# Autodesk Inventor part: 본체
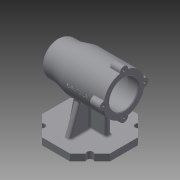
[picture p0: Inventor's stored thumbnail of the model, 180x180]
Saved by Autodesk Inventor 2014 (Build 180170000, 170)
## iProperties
Created: 2021-01
Part Number: 본체
Material: Generic
Document SubType Name: Modeling
Designer: kh
Density: 1 g/cm^3
Appearance: Default
Author: kh
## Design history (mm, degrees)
sketch "Sketch1" dims "d0" = 100
  geometry: L1 (20.711, 50)-(50, 20.711); L2 (50, 20.711)-(50, -20.711); L3 (50, -20.711)-(20.711, -50); L4 (20.711, -50)-(-20.711, -50); L5 (-20.711, -50)-(-50, -20.711); L6 (-50, -20.711)-(-50, 20.711); L7 (-50, 20.711)-(-20.711, 50); L8 (-20.711, 50)-(20.711, 50); 4 further points
  constraints: 16 end point, 2 coincident, 1 horizontal, 1 midpoint, 1 vertical alignment, 19 other
extrude "Extrusion1" new body sketch "Sketch1" distance "d1" = 10; taper "d2" = 0 deg
sketch "Sketch2"
  geometry: L1 (50, 20.711)-(20.711, 50) reference; L2 (20.711, 50)-(-20.711, 50) reference; L3 (-20.711, 50)-(-50, 20.711) reference; L4 (-50, 20.711)-(-50, -20.711) reference; L5 (-50, -20.711)-(-20.711, -50) reference; L6 (-20.711, -50)-(20.711, -50) reference; L7 (20.711, -50)-(50, -20.711) reference; L8 (50, -20.711)-(50, 20.711) reference; L9 (-35.355, 35.355)-(35.355, -35.355); L10 (35.355, 35.355)-(-35.355, -35.355); C1 r 4.5 at (35.355, 35.355); C2 r 4.5 at (35.355, -35.355); C3 r 4.5 at (-35.355, -35.355); C4 r 4.5 at (-35.355, 35.355); 2 further points
  constraints: 5 midpoint, 4 centre point, 4 coincident, 4 end point, 2 perpendicular, 1 point on line
  dimensions: "d3" = 9 diameter of C1; "d4" = 9 diameter of C2; "d5" = 9 diameter of C3; "d6" = 9 diameter of C4
extrude "Extrusion2" cut sketch "Sketch2" stored distance "d7" = 0; taper "d8" = 0 deg
sketch "Sketch3"
  geometry: L1 (0, 0)-(0, 75); L2 (-50, 0)-(-50, 10) reference; L3 (-50, 75)-(50, 75); L4 (50, 75)-(50, 100); L5 (50, 100)-(30, 100); L6 (30, 100)-(10, 105); L7 (10, 105)-(-50, 105); L8 (-50, 105)-(-50, 75); L9 (-50, 96)-(-35, 96); L10 (-35, 96)-(-35, 75); L11 (-35, 75)-(-50, 75); L12 (-50, 75)-(-50, 96); L13 (-35, 75)-(7, 75); L14 (7, 75)-(7, 99); L15 (7, 99)-(-35, 99); L16 (-35, 99)-(-35, 75); L17 (7, 75)-(19, 75); L18 (19, 75)-(19, 96); L19 (19, 96)-(7, 96); L20 (7, 96)-(7, 75); L21 (19, 75)-(37, 75); L22 (37, 75)-(37, 92.5); L23 (37, 92.5)-(19, 92.5); L24 (19, 92.5)-(19, 75); L25 (37, 75)-(41, 75); L26 (41, 75)-(41, 91); L27 (41, 91)-(37, 91); L28 (37, 91)-(37, 75); L29 (41, 75)-(44, 75); L30 (44, 75)-(44, 85.5); L31 (44, 85.5)-(41, 85.5); L32 (41, 85.5)-(41, 75)
  constraints: 62 end point, 15 parallel, 8 perpendicular, 6 horizontal, 2 point on line, 1 collinear, 1 midpoint, 1 vertical
  dimensions: "d9" = 75 distance of L1.start L1.end; "d10" = 60 diameter of L7 L3; "d11" = 50 diameter of L5 L3; "d12" = 20 distance from line of L5.end L4; "d13" = 40 distance from line of L6.end L4; "d14" = 100 distance between parallel lines of L8 L4; "d15" = 15 distance between parallel lines of L8 L10; "d16" = 42 distance between parallel lines of L10 L20; "d17" = 12 distance between parallel lines of L20 L24; "d18" = 18 distance between parallel lines of L24 L22; "d19" = 4 distance of L26.end L27.end; "d20" = 3 distance of L30.end L31.end; "d21" = 21 diameter of L31 L3; "d22" = 32 diameter of L27 L3; "d23" = 35 diameter of L23 L3; "d24" = 48 diameter of L15 L13; "d25" = 42 diameter of L19 L17; "d26" = 42 diameter of L9 L3
revolve "Revolution1" sketch "Sketch3" stored, may be unused: angle "d27" = 90 deg
sketch "Sketch4"
  geometry: L1 (-30, 0)-(30, 0); L2 (0, 30)-(0, -30); C1 r 6 at (-30, 0); C2 r 6 at (0, 30); C3 r 6 at (30, 0); C4 r 6 at (0, -30); A1 r 30 centre (0, 0) between (0, -30) and (-30, 0) reference; 2 further points
  constraints: 5 coincident, 4 centre point, 4 end point, 2 midpoint, 2 point on circle, 1 horizontal, 1 perpendicular
  dimensions: "d28" = 12 diameter of C1; "d29" = 12 diameter of C2 (= d28); "d30" = 12 diameter of C3 (= d28); "d31" = 12 diameter of C4 (= d28)
extrude "Extrusion3" join sketch "Sketch4" distance "d32" = 16; taper "d33" = 0 deg
sketch "Sketch5"
  geometry: L1 (20.711, 0)-(-20.711, 0) reference; L2 (-27, 0)-(-27, 51); L3 (-50, 0)-(-50, 10) reference; L4 (27, 10)-(19.03, 51); L5 (38.537, 10)-(50, 10) reference; L6 (20.711, 10)-(32.173, 10) reference; L7 (50, 0)-(50, 10) reference; L8 (27, 10)-(-27, 10); L9 (19.03, 51)-(-27, 51); L10 (-35, 51)-(7, 51) reference; 1 further point
  constraints: 8 end point, 4 point on line, 2 perpendicular, 1 parallel
  dimensions: "d34" = 23 distance between parallel lines of L3 L2; "d35" = 101 deg angle of L5 L4; "d36" = 23 distance from line of L4.start L7
extrude "Extrusion4" join sketch "Sketch5" stored distance "d37" = 8; taper "d38" = 0 deg
sketch "Sketch6"
  geometry: L1 (-35, 10)-(-23.246, 42.294); L2 (23.02, 42.915)-(35, 10); L3 (0, 0)-(0, 55.467); L4 (-38.537, 10)-(-30.855, 10) reference; L5 (-20.711, 10)-(-32.173, 10) reference; L6 (50, 10)-(38.537, 10) reference; L7 (30.855, 10)-(38.537, 10) reference; L8 (-50, 0)-(-50, 10) reference; 1 further point
  constraints: 6 end point, 2 point on line, 1 vertical, 1 other
  dimensions: "d39" = 15 distance from line of L8 L1.start; "d40" = 110 deg angle of L4 L1
feature "Rib1" dims "d41" = 1, "d42" = 8, "d43" = 0, "d44" = 0, "d45" = 1, "d46" = 1
feature "Rib2" dims "d47" = 1, "d48" = 8, "d49" = 0, "d50" = 0, "d51" = 1, "d52" = 1
sketch "Sketch7"
  geometry: L1 (0, 0)-(60, 0); L2 (30, 30)-(30, -30); A1 r 30 centre (30, 0) between (24.03, 29.4) and (0.6, 5.97) reference; A2 r 30 centre (30, 0) between (30, 30) and (0, 0); 7 further points
  constraints: 7 coincident, 4 end point, 2 midpoint, 2 point on circle, 1 centre point, 1 concentric, 1 horizontal, 1 perpendicular
hole "Hole1" sketch "Sketch7" at (0, 0), (30, -30), (60, 0), (30, 30) diameter "d53" = 3.242; stored, may be unused: countersink angle "d57" = 90 deg, drill point angle "d59" = 118 deg; dims "d54" = 8, "d55" = 4, "d56" = 2, "d58" = 10
fillet "Fillet1" dims "d60" = 0.3, "d61" = 3
fillet "Fillet2" dims "d62" = 1, "d63" = 10, "d64" = 3
fillet "Fillet3" dims "d65" = 3
fillet "Fillet4" dims "d66" = 3
workplane "Work Plane2"
  workplane "Work Plane1"
sketch "Sketch8"
  geometry: L1 (-24.592, 2.402)-(8.592, 2.402); L2 (8.592, 2.402)-(8.592, -2.402); L3 (8.592, -2.402)-(-24.592, -2.402); L4 (-24.592, -2.402)-(-24.592, 2.402); L5 (-24.592, 2.402)-(8.592, -2.402); L6 (30, 29.226)-(30, 6.771) reference; L7 (-70, -15)-(-70, 15) reference; L8 (-70, 0)-(30, 0); 2 further points
  constraints: 4 end point, 2 midpoint, 1 perpendicular, 1 point on line, 2 other
  dimensions: "d68" = 38 distance from line of L6 point (-8, 0)
emboss "Emboss1" sketch "Sketch8" dims "d0" = 100, "d69" = 0.5, "d70" = 0
chamfer "Chamfer1" distance "d71" = 1; stored, may be unused: second distance "d72" = 2, angle "d73" = 45 deg
body "Solid1"
node "Projected Loop1"
other parameters: "d67" = 0.5
